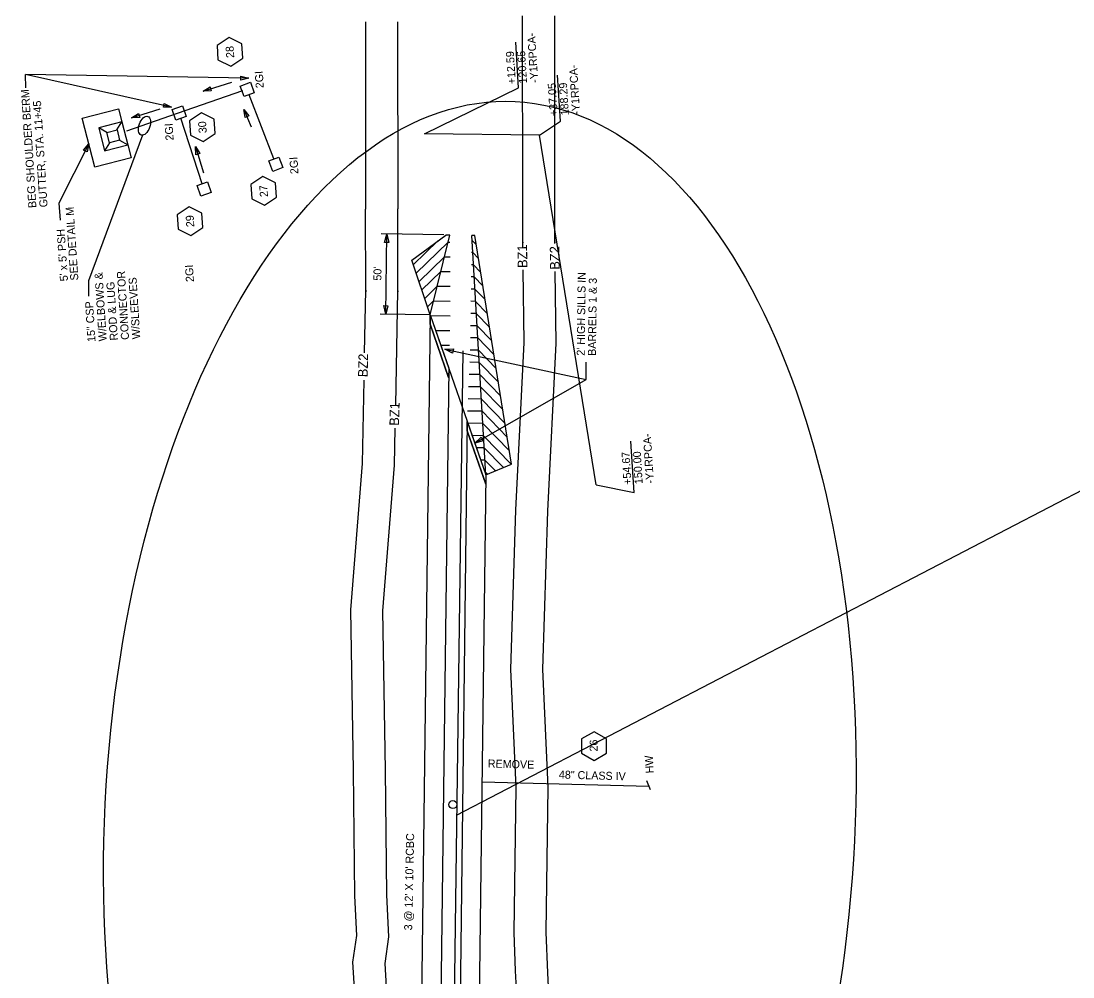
# Model space of a CAD drawing. Extents: x 2384780 to 2405432, y 547869 to 573706.
# Drawn here: x 2395469 to 2396126, y 555252 to 555848 of the extents above; entities that cross this region are included whole.
import ezdxf

# ---------------------------------------------------------------- set-up
doc = ezdxf.new("R2010")
doc.units = 0
for name, color, linetype in [('Old_Level_1', 7, 'Continuous'), ('Old_Level_10', 7, 'Continuous'), ('Old_Level_23', 7, 'Continuous'), ('Old_Level_5', 7, 'Continuous'), ('Old_Level_59', 7, 'Continuous'), ('Old_Level_63', 7, 'Continuous'), ('Old_Level_9', 7, 'Continuous'), ('Prop Buffer Zone 1', 7, 'Continuous'), ('Prop Buffer Zone 2', 7, 'Continuous'), ('Prop Drainage Box Number Symbol CELL', 7, 'Continuous'), ('Prop Drop Inlet Text', 7, 'Continuous')]:
    doc.layers.add(name, color=color, linetype=linetype)

# ---------------------------------------------------------------- blocks, each defined once
blk = doc.blocks.new('IN')
at = {"layer": 'Old_Level_9'}
blk.add_lwpolyline([(-0.07025, 0.067), (0.07025, 0.067), (0.07025, -0.067), (-0.07025, -0.067)], close=True, dxfattribs=at)
blk = doc.blocks.new('BUBBLE')
at = {"layer": 'Old_Level_10'}
blk.add_ellipse((0, 0), major_axis=(192, 154), ratio=0.548538, dxfattribs=at)

msp = doc.modelspace()

# ---------------------------------------------------------------- linework, layer by layer
at = {"layer": 'Old_Level_1'}
for p, q in [((2395607.7, 555804.67), (2395567.01, 555790.54)), ((2395627.35, 555762.19), (2395611.98, 555802.34)), ((2395530.24, 555793.53), (2395532.34, 555785.37)), ((2395529.33, 555780.33), (2395532.34, 555785.37)), ((2395567.01, 555790.54), (2395535.23, 555779.49)), ((2395582.6, 555746.74), (2395569.31, 555787.62)), ((2395522.98, 555778.68), (2395517.93, 555781.66)), ((2395524.63, 555772.31), (2395521.63, 555767.27)), ((2395530.99, 555773.97), (2395536.05, 555770.98)), ((2395536.05, 555770.98), (2395538.14, 555762.83)), ((2395757.29, 555373.43), (2395861.67, 555370.65))]:
    msp.add_line(p, q, dxfattribs=at)
for points in [[(2395538.14, 555762.83), (2395515.57, 555757.02), (2395507.67, 555787.73), (2395530.24, 555793.53)], [(2395532.34, 555785.37), (2395517.93, 555781.66), (2395521.63, 555767.27), (2395536.05, 555770.98)], [(2395532.34, 555785.37), (2395536.05, 555770.98)], [(2395734.04, 555643.48), (2395822.28, 555624.6)], [(2395752.85, 555584.72), (2395822.28, 555624.6), (2395822.41, 555635.27)]]:
    msp.add_lwpolyline(points, dxfattribs=at)
for points in [[(2395530.99, 555773.97), (2395524.62, 555772.33), (2395522.98, 555778.68), (2395529.36, 555780.32)], [(2395738.93, 555641.08), (2395734.04, 555643.48), (2395739.48, 555643.66)], [(2395758.09, 555586.21), (2395752.85, 555584.72), (2395756.77, 555588.49)]]:
    msp.add_lwpolyline(points, close=True, dxfattribs=at)
at = {"layer": 'Old_Level_10'}
for p, q in [((2395733.38, 555714.89), (2395694.41, 555715.38)), ((2395697.16, 555665.34), (2395697.79, 555715.33)), ((2395724.96, 555664.99), (2395737.17, 555714.7)), ((2395737.17, 555714.7), (2395734.65, 555714.73)), ((2395752.73, 555714.5), (2395750.85, 555714.53)), ((2395759.7, 555565), (2395750.85, 555714.53)), ((2395775.79, 555571.8), (2395752.73, 555714.5)), ((2395714.39, 555696.19), (2395729.62, 555711.04)), ((2395716.17, 555690.94), (2395736.11, 555710.38)), ((2395736.11, 555710.38), (2395737.24, 555710.37)), ((2395753.66, 555708.77), (2395751.03, 555711.46)), ((2395717.95, 555685.69), (2395733.85, 555701.2)), ((2395733.85, 555701.2), (2395737.33, 555701.16)), ((2395751.48, 555703.83), (2395750.78, 555703.84)), ((2395755.04, 555700.18), (2395751.48, 555703.83)), ((2395751.94, 555696.21), (2395750.68, 555696.22)), ((2395756.43, 555691.6), (2395751.94, 555696.21)), ((2395719.73, 555680.45), (2395731.6, 555692.02)), ((2395731.6, 555692.02), (2395737.42, 555691.95)), ((2395752.39, 555688.58), (2395750.58, 555688.6)), ((2395757.82, 555683.01), (2395752.39, 555688.58)), ((2395721.51, 555675.2), (2395729.35, 555682.84)), ((2395729.35, 555682.84), (2395737.51, 555682.74)), ((2395752.84, 555680.96), (2395750.47, 555680.99)), ((2395759.21, 555674.43), (2395752.84, 555680.96)), ((2395723.28, 555669.95), (2395727.09, 555673.66)), ((2395727.09, 555673.66), (2395737.47, 555673.53)), ((2395753.29, 555673.33), (2395750.37, 555673.37)), ((2395760.59, 555665.84), (2395753.29, 555673.33)), ((2395724.96, 555664.99), (2395693.78, 555665.38)), ((2395724.96, 555664.99), (2395718.02, 555115.19)), ((2395724.96, 555664.99), (2395759.7, 555565)), ((2395725.14, 555664.48), (2395737.34, 555664.32)), ((2395753.74, 555665.71), (2395750.26, 555665.75)), ((2395761.98, 555657.26), (2395753.74, 555665.71)), ((2395724.89, 555659.11), (2395736.47, 555625.78)), ((2395728.36, 555655.23), (2395737.21, 555655.11)), ((2395754.19, 555658.08), (2395750.16, 555658.13)), ((2395763.37, 555648.67), (2395754.19, 555658.08)), ((2395754.64, 555650.46), (2395750.06, 555650.51)), ((2395764.75, 555640.09), (2395754.64, 555650.46)), ((2395731.57, 555645.98), (2395737.09, 555645.91)), ((2395755.1, 555642.83), (2395749.95, 555642.9)), ((2395766.14, 555631.5), (2395755.1, 555642.83)), ((2395755.55, 555635.21), (2395749.62, 555635.28)), ((2395767.53, 555622.92), (2395755.55, 555635.21)), ((2395736.54, 555631.66), (2395729.6, 555081.86)), ((2395756, 555627.58), (2395749.27, 555627.67)), ((2395768.92, 555614.33), (2395756, 555627.58)), ((2395756.45, 555619.95), (2395748.93, 555620.05)), ((2395770.3, 555605.75), (2395756.45, 555619.95)), ((2395756.9, 555612.33), (2395748.58, 555612.44)), ((2395771.69, 555597.16), (2395756.9, 555612.33)), ((2395757.35, 555604.7), (2395748.24, 555604.82)), ((2395773.08, 555588.58), (2395757.35, 555604.7)), ((2395748.12, 555598.33), (2395741.18, 555048.53)), ((2395757.8, 555597.08), (2395747.89, 555597.2)), ((2395774.47, 555579.99), (2395757.8, 555597.08)), ((2395748.05, 555592.45), (2395759.63, 555559.12)), ((2395758.26, 555589.45), (2395750.77, 555589.55)), ((2395775.57, 555571.7), (2395758.26, 555589.45)), ((2395758.71, 555581.83), (2395753.83, 555581.89)), ((2395770.62, 555569.61), (2395758.71, 555581.83)), ((2395759.16, 555574.2), (2395756.49, 555574.24)), ((2395765.68, 555567.52), (2395759.16, 555574.2)), ((2395759.7, 555565), (2395775.79, 555571.8)), ((2395759.7, 555565), (2395752.76, 555015.2)), ((2395760.73, 555565.43), (2395759.61, 555566.58))]:
    msp.add_line(p, q, dxfattribs=at)
for points in [[(2395713.39, 555699.14), (2395734.65, 555714.73)], [(2395724.96, 555664.99), (2395713.39, 555699.14)]]:
    msp.add_lwpolyline(points, dxfattribs=at)
for points in [[(2395736.47, 555625.78), (2395724.89, 555659.11), (2395724.96, 555664.99), (2395736.54, 555631.66)], [(2395759.63, 555559.12), (2395748.05, 555592.45), (2395748.12, 555598.33), (2395759.7, 555565)]]:
    msp.add_lwpolyline(points, close=True, dxfattribs=at)
at = {"layer": 'Old_Level_23'}
for points in [[(2395696.4, 555710.07), (2395697.79, 555715.33), (2395699.04, 555710.04)], [(2395698.55, 555670.6), (2395697.16, 555665.34), (2395695.91, 555670.64)]]:
    msp.add_lwpolyline(points, close=True, dxfattribs=at)
msp.add_circle((2395739.1, 555359.21), 2.5, dxfattribs=at)
at = {"layer": 'Old_Level_5'}
for p, q in [((2395563.45, 555794.59), (2395472.25, 555815.01)), ((2395611.67, 555812.62), (2395472.25, 555815.01)), ((2395472.36, 555806.55), (2395472.25, 555815.01)), ((2395583.11, 555804.49), (2395601.02, 555810.15)), ((2395538.45, 555787.84), (2395556.36, 555793.51)), ((2395608.6, 555793.17), (2395613.14, 555782.36)), ((2395511.79, 555771.71), (2395493.12, 555734.7)), ((2395578.41, 555770.04), (2395583.32, 555753.46)), ((2395493.12, 555734.7), (2395493.79, 555724)), ((2395862.56, 555368.44), (2395860.17, 555374.12))]:
    msp.add_line(p, q, dxfattribs=at)
for points in [[(2395606.69, 555813.96), (2395611.67, 555812.62), (2395606.65, 555811.46)], [(2395588.25, 555804.8), (2395583.11, 555804.49), (2395587.5, 555807.19)], [(2395558.84, 555796.91), (2395563.45, 555794.59), (2395558.3, 555794.47)], [(2395609.38, 555788.08), (2395608.6, 555793.17), (2395611.68, 555789.05)], [(2395543.59, 555788.16), (2395538.45, 555787.84), (2395542.84, 555790.54)], [(2395508.47, 555767.77), (2395511.79, 555771.71), (2395510.71, 555766.67)], [(2395578.63, 555764.89), (2395578.41, 555770.04), (2395581.03, 555765.6)]]:
    msp.add_lwpolyline(points, close=True, dxfattribs=at)
msp.add_lwpolyline([(2395545.21, 555777.06), (2395511.58, 555686.15), (2395511.63, 555676.48)], dxfattribs=at)
at = {"layer": 'Old_Level_59'}
msp.add_line((2395745.22, 555642.53), (2395736.63, 554993.16), dxfattribs=at)
at = {"layer": 'Old_Level_63'}
for p, q in [((2395793.28, 555776.99), (2395721.36, 555777.91)), ((2395828.53, 555558.87), (2395793.28, 555776.99))]:
    msp.add_line(p, q, dxfattribs=at)
for points in [[(2395741.38, 555352.65), (2397486.2, 556259.18), (2397969.34, 556307.66)], [(2395721.36, 555777.91), (2395780.13, 555806.62), (2395778.36, 555835.19)], [(2395793.28, 555776.99), (2395806.31, 555785.89), (2395804.54, 555814.46)], [(2395828.53, 555558.87), (2395852.32, 555554.03), (2395850.34, 555585.96)]]:
    msp.add_lwpolyline(points, dxfattribs=at)
msp.add_ellipse((2395755.96, 555348.13), major_axis=(22.11, 449.92), ratio=0.519952, dxfattribs=at)
at = {"layer": 'Prop Buffer Zone 1'}
for p, q in [((2395782.7, 555710.28), (2395782.71, 555709.81)), ((2395704.7, 555679.93), (2395704.69, 555679.35)), ((2395781.22, 555198.41), (2395778.29, 555255.46))]:
    msp.add_line(p, q, dxfattribs=at)
for points in [[(2395782.7, 555730.8), (2395782.68, 555851.65)], [(2395704.49, 555847.89), (2395704.63, 555730.98)], [(2395704.69, 555679.35), (2395704.63, 555730.98)], [(2395782.71, 555709.81), (2395782.7, 555730.8)], [(2395782.76, 555706.73), (2395782.7, 555710.28)], [(2395778.29, 555255.46), (2395777.29, 555279.28), (2395778.61, 555369.78), (2395775.34, 555443.67), (2395778.49, 555543.08), (2395783.69, 555647.63), (2395782.98, 555693.04)], [(2395703.4, 555608.49), (2395704.7, 555679.93)], [(2395692.31, 555202.2), (2395697.58, 555245.43), (2395696.76, 555260.03), (2395699.15, 555276.66), (2395697.78, 555302.87), (2395697, 555380.76), (2395695.32, 555480.05), (2395702.73, 555571.07), (2395703.15, 555594.24)]]:
    msp.add_lwpolyline(points, dxfattribs=at)
at = {"layer": 'Prop Buffer Zone 2'}
for p, q in [((2395802.7, 555710.6), (2395802.71, 555709.82)), ((2395684.7, 555680.29), (2395684.69, 555679.32)), ((2395801.21, 555197.98), (2395798.35, 555254.26))]:
    msp.add_line(p, q, dxfattribs=at)
for points in [[(2395802.7, 555730.8), (2395802.68, 555851.65)], [(2395684.49, 555847.86), (2395684.63, 555730.96)], [(2395684.69, 555679.32), (2395684.63, 555730.96)], [(2395802.71, 555709.82), (2395802.7, 555730.8)], [(2395802.72, 555709.51), (2395802.7, 555710.6)], [(2395798.35, 555254.26), (2395797.3, 555279.55), (2395798.61, 555370.08), (2395795.35, 555443.8), (2395798.48, 555542.27), (2395803.7, 555647.29), (2395803, 555691.89)], [(2395683.99, 555641.16), (2395684.7, 555680.29)], [(2395672.31, 555202.67), (2395677.61, 555244.31), (2395676.68, 555260.9), (2395679.08, 555277.57), (2395677.78, 555302.24), (2395677, 555380.49), (2395675.31, 555480.69), (2395682.74, 555572.06), (2395683.68, 555624.11)]]:
    msp.add_lwpolyline(points, dxfattribs=at)
at = {"layer": 'Prop Drainage Box Number Symbol CELL'}
msp.add_lwpolyline([(2395827.27, 555404.71), (2395819.52, 555400.23), (2395819.52, 555391.28), (2395827.27, 555386.81), (2395835.02, 555391.28), (2395835.02, 555400.23)], close=True, dxfattribs=at)
at = {"layer": 'Prop Drop Inlet Text'}
for points in [[(2395599.3, 555837.96), (2395591.84, 555833.01), (2395592.41, 555824.08), (2395600.42, 555820.1), (2395607.87, 555825.05), (2395607.31, 555833.98)], [(2395582.11, 555791.01), (2395574.66, 555786.06), (2395575.22, 555777.13), (2395583.23, 555773.15), (2395590.69, 555778.1), (2395590.13, 555787.03)], [(2395620.34, 555751.21), (2395612.89, 555746.26), (2395613.45, 555737.33), (2395621.46, 555733.35), (2395628.92, 555738.3), (2395628.36, 555747.23)], [(2395574.35, 555732.36), (2395566.9, 555727.41), (2395567.46, 555718.48), (2395575.47, 555714.5), (2395582.93, 555719.45), (2395582.37, 555728.38)]]:
    msp.add_lwpolyline(points, close=True, dxfattribs=at)

# ---------------------------------------------------------------- block references
at = {"layer": 'Old_Level_5'}
for name, p, xscale, yscale, rotation in [('IN', (2395610.73, 555805.63), 49.99999999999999, 49.999999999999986, 110.73804622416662), ('IN', (2395568.16, 555790.94), 50, 49.99999999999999, 109.15938382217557), ('BUBBLE', (2395546.55, 555782.97), 0.025, 0.025000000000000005, 31.87517703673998), ('IN', (2395628.6, 555758.9), 49.99999999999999, 49.999999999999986, 110.73804622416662), ('IN', (2395583.75, 555743.42), 50, 49.99999999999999, 109.15938382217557)]:
    msp.add_blockref(name, p, dxfattribs=dict(at, xscale=xscale, yscale=yscale, rotation=rotation))

# ---------------------------------------------------------------- texts
at = {"layer": 'Old_Level_1'}
for s, rotation, p in [("50'", 89.27663, (2395694.45, 555686.25)), ("2' HIGH SILLS IN", 89.27663, (2395821.42, 555639.38)), ('BARRELS 1 & 3', 89.27663, (2395828.42, 555639.29)), ('REMOVE', 358.47277, (2395760.88, 555382.39)), ('HW', 93.59361, (2395864.6, 555378.89)), ('48" CLASS IV', 358.4728, (2395805.25, 555375.49)), ("3 @ 12' X 10' RCBC", 88.79152, (2395713.66, 555280.66))]:
    msp.add_text(s, height=5, rotation=rotation, dxfattribs=at).set_placement(p)
at = {"layer": 'Old_Level_5'}
for s, rotation, p in [('2GI', 93.59359, (2395621.02, 555806.53)), ('BEG SHOULDER BERM', 93.59359, (2395479.03, 555731.73)), ('GUTTER, STA. 11+45', 93.59359, (2395486.02, 555732.17)), ('2GI', 93.59359, (2395564.73, 555773.89)), ('2GI', 93.59359, (2395642.67, 555752.94)), ('SEE DETAIL M', 93.80188, (2395505.25, 555686.51)), ("5' x 5' PSH", 93.80188, (2395498.77, 555686.07)), ('2GI', 93.59359, (2395577.41, 555685.6)), ('W/ELBOWS &', 93.59359, (2395522.96, 555648.59)), ('CONNECTOR', 93.59359, (2395536.93, 555649.47)), ('W/SLEEVES', 93.59359, (2395543.92, 555649.9)), ('ROD & LUG', 93.59359, (2395529.94, 555649.03)), ('15" CSP', 93.59359, (2395515.97, 555648.15))]:
    msp.add_text(s, height=5, rotation=rotation, dxfattribs=at).set_placement(p)
at = {"layer": 'Old_Level_63'}
for s, p in [('-Y1RPCA-', (2395792.42, 555809.91)), ('+12.59', (2395778.45, 555809.05)), ('120.65', (2395785.43, 555809.48)), ('-Y1RPCA-', (2395818.55, 555790.02)), ('+37.05', (2395804.58, 555789.16)), ('188.29', (2395811.56, 555789.59)), ('-Y1RPCA-', (2395864.67, 555559.86)), ('+54.67', (2395850.69, 555558.99)), ('150.00', (2395857.68, 555559.42))]:
    msp.add_text(s, height=5, rotation=93.54432, dxfattribs=at).set_placement(p)
at = {"layer": 'Prop Buffer Zone 1'}
for rotation, p in [(90.8948, (2395785.65, 555694.21)), (88.54994, (2395705.46, 555595.6))]:
    msp.add_text('BZ1', height=6, rotation=rotation, dxfattribs=at).set_placement(p)
at = {"layer": 'Prop Buffer Zone 2'}
for rotation, p in [(90.8948, (2395805.84, 555693.13)), (88.54994, (2395685.84, 555625.93))]:
    msp.add_text('BZ2', height=6, rotation=rotation, dxfattribs=at).set_placement(p)
at = {"layer": 'Prop Drop Inlet Text'}
for s, rotation, p in [('28', 93.59359, (2395602.59, 555825.43)), ('30', 93.59359, (2395585.41, 555778.44)), ('27', 93.59359, (2395623.64, 555738.61)), ('29', 93.59359, (2395577.64, 555719.85)), ('26', 90.34582, (2395829.53, 555392.35))]:
    msp.add_text(s, height=5, rotation=rotation, dxfattribs=at).set_placement(p)

doc.saveas('drawing.dxf')
